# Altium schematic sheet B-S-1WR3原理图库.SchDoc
size 127 x 99 mm
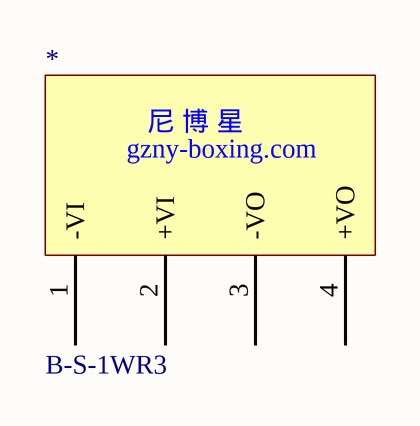
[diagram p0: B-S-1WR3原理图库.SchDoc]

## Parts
*  B-S-1WR3

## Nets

Not connected (* = marked no-connect by the designer): * 1(-VI) 2(+VI) 3(-VO) 4(+VO)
